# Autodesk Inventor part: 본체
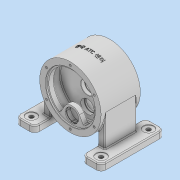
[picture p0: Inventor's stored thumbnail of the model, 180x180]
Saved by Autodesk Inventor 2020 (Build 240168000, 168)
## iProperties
Created: 2025-12
Part Number: 본체
Material: 일반
Document SubType Name: Modeling
Designer: PC2-06
Density: 1 g/cm^3
Appearance: 기본값
Mass: 2121.14 g
Surface Area: 3029.78 cm^2
Volume: 2121.14 cm^3
Author: PC2-06
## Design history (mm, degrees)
sketch "스케치1"
  geometry: L1 (0, 62)-(0, -62); L2 (0, 62)-(78, 62); L3 (78, 62)-(78, 57); L4 (78, 57)-(73, 57); L5 (73, 57)-(73, 43); L6 (76, 40)-(84, 40); L7 (87, 37)-(87, 11); L8 (84, 8)-(21, 8); L9 (21, 8)-(21, -3.4); L10 (20.4, -4)-(19, -4); L11 (19, -4)-(19, -8); L12 (19, -8)-(84, -8); L13 (87, -11)-(87, -37); L14 (84, -40)-(73, -40); L15 (73, -40)-(73, -57); L16 (73, -57)-(78, -57); L17 (78, -57)-(78, -62); L18 (78, -62)-(0, -62); L19 (78, 62)-(97, 62); L20 (97, 62)-(97, -62); L21 (97, -62)-(78, -62); L22 (76, 40)-(73, 40); L23 (73, 40)-(73, 43); A1 r 0.6 centre (20.4, -3.4) between (20.4, -4) and (21, -3.4); A2 r 3 centre (84, 37) between (87, 37) and (84, 40); A3 r 3 centre (84, 11) between (84, 8) and (87, 11); A4 r 3 centre (84, -11) between (87, -11) and (84, -8); A5 r 3 centre (84, -37) between (84, -40) and (87, -37); 7 further points
  constraints: 47 end point, 16 perpendicular, 14 point on line, 10 point on circle, 10 tangent, 5 centre point, 3 horizontal, 1 coincident, 1 collinear, 1 midpoint, 1 vertical
  dimensions: "d0" = 156 diameter of L3 L1; "d1" = 146 diameter of L5 L1; "d2" = 174 diameter of L7 L1; "d3" = 42 diameter of L9 L1; "d4" = 38 diameter of L11 L1; "d5" = 174 diameter of L13 L1; "d6" = 5 distance between parallel lines of L4 L2; "d7" = 22 distance between parallel lines of L2 L6; "d8" = 32 distance between parallel lines of L8 L6; "d9" = 32 distance between parallel lines of L14 L12; "d10" = 22 distance between parallel lines of L18 L14; "d11" = 5 distance between parallel lines of L18 L16; "d12" = 124 distance between parallel lines of L18 L2; "d13" = 12 distance between parallel lines of L10 L8; "d14" = 194 diameter of L20 L1; "d16" = 0.6 radius of A1 (derived)
revolve "회전1" sketch "스케치1" stored, may be unused: angle "d15" = 90 deg
sketch "스케치2"
  geometry: L1 (-21, -3.4)-(21, -3.4) reference; L2 (-21, 8)-(21, 8) reference; L3 (-19, -8)-(19, -8) reference; L4 (-19, -4)-(19, -4) reference; L5 (-84, 8)-(84, 8) reference; L6 (-31.5, 8)-(-31.5, -2.768); L7 (-32.1, -3.368)-(-33.5, -3.368); L8 (-33.5, -3.368)-(-33.5, -8); L9 (-52.5, 8)-(-52.5, -8); L10 (-84, -8)-(84, -8) reference; A1 r 0.6 centre (-32.1, -2.768) between (-32.1, -3.368) and (-31.5, -2.768); 1 further point
  constraints: 8 end point, 3 perpendicular, 3 point on line, 2 point on circle, 2 tangent, 1 centre point, 1 vertical
  dimensions: "d18" = 42 diameter of L6 L9; "d19" = 38 diameter of L8 L9; "d20" = 52.5 horizontal distance of L9.end point (0, 0); "d21" = 0.6 radius of A1
revolve "회전2" sketch "스케치2" stored, may be unused: angle "d22" = 90 deg
sketch "스케치3"
  geometry: L1 (23.383, -39)-(39.648, -67.172); L2 (-23.383, -39)-(-39.648, -67.172); C1 r 21 at (0, -52.5) reference; C2 r 21 at (0, -52.5); A1 r 27 centre (0, -52.5) between (23.383, -39) and (-23.383, -39); A2 r 78 centre (0, 0) between (39.648, -67.172) and (-39.648, -67.172) reference; 1 further point
  constraints: 4 end point, 4 point on circle, 2 centre point, 2 coincident, 2 tangent, 1 horizontal alignment
  dimensions: "d23" = 54 diameter of A1; "d24" = 42 diameter of C2; "d25" = 60 deg angle of L1 L2
extrude "돌출1" join sketch "스케치3" distance "d26" = 17; taper "d27" = 0 deg
fillet "모깎기1" dims "d30" = 3
node "작업 평면1"
sketch "스케치4"
  geometry: L1 (120, -100)-(90, -100); L2 (75, -85)-(75, 85); L3 (90, 100)-(120, 100); L4 (135, 85)-(135, -85); L5 (-90, -100)-(-120, -100); L6 (-135, -85)-(-135, 85); L7 (-120, 100)-(-90, 100); L8 (-75, 85)-(-75, -85); A1 r 15 centre (120, -85) between (120, -100) and (135, -85); A2 r 15 centre (120, 85) between (135, 85) and (120, 100); A3 r 15 centre (90, 85) between (90, 100) and (75, 85); A4 r 15 centre (90, -85) between (75, -85) and (90, -100); A5 r 15 centre (-90, -85) between (-90, -100) and (-75, -85); A6 r 15 centre (-120, -85) between (-135, -85) and (-120, -100); A7 r 15 centre (-120, 85) between (-120, 100) and (-135, 85); A8 r 15 centre (-90, 85) between (-75, 85) and (-90, 100); 3 further points
  constraints: 16 end point, 16 point on circle, 16 tangent, 8 centre point, 7 equal radius, 4 parallel, 2 horizontal, 2 horizontal alignment, 2 midpoint, 2 perpendicular
  dimensions: "d32" = 200 distance between parallel lines of L3 L1; "d33" = 60 distance between parallel lines of L2 L4; "d34" = 60 distance between parallel lines of L6 L8; "d35" = 15 radius of A1; "d36" = 200 distance between parallel lines of L7 L5; "d37" = 150 distance between parallel lines of L8 L2; "d38" = 75 distance from line of L2 point (0, 0)
extrude "돌출3" join sketch "스케치4" distance "d39" = 20; taper "d40" = 0 deg
sketch "스케치5"
  geometry: L1 (-75, -85)-(-75, 85) reference; L2 (-75, 50)-(-97, 50); L3 (-97, 50)-(-97, -50); L4 (-97, -50)-(-75, -50); L5 (-75, -50)-(-75, 50); L6 (75, 85)-(75, -85) reference; L7 (75, 50)-(97, 50); L8 (97, 50)-(97, -50); L9 (97, -50)-(75, -50); L10 (75, -50)-(75, 50); 5 further points
  constraints: 16 end point, 4 parallel, 2 horizontal, 2 horizontal alignment, 2 midpoint, 2 perpendicular, 2 point on line
  dimensions: "d41" = 22 distance of L4.end L3.end; "d42" = 100 distance of L3.end L2.end; "d43" = 22 distance between parallel lines of L8 L6; "d44" = 100 distance between parallel lines of L9 L7
extrude "돌출4" join sketch "스케치5" stored distance "d45" = 20; taper "d46" = 0 deg
sketch "스케치6"
  geometry: 5 further points
  constraints: 2 vertical alignment, 1 horizontal alignment
  dimensions: "d47" = 150 distance of point (-110, -75) point (-110, 75); "d48" = 150 distance of point (110, -75) point (110, 75); "d49" = 220 distance of point (110, -75) point (-110, -75); "d50" = 110 horizontal distance of point (110, -75) point (0, 0); "d51" = 75 vertical distance of point (0, 0) point (-110, 75)
hole "구멍1" sketch "스케치6" at (-110, 75), (-110, -75), (110, -75), (110, 75) diameter "d52" = 13.5; stored, may be unused: countersink angle "d56" = 82 deg, drill point angle "d58" = 118 deg; dims "d53" = 6, "d54" = 33, "d55" = 2, "d57" = 8
sketch "스케치7"
  geometry: L1 (-75, -120)-(-75, -100) reference; L2 (-75, -112)-(-36.6, -89.83); L3 (-135.8, -120)-(135.8, -120) reference; L4 (-75, -100)-(-75, -61.514) reference; A1 r 97 centre (0, 0) between (-36.6, -89.83) and (-75, -61.514) reference; 1 further point
  constraints: 2 end point, 1 point on circle, 1 point on line
  dimensions: "d59" = 8 distance from line of L3 L2.start; "d60" = 60 deg angle of L2 L4
sketch "스케치8"
  geometry: L1 (-31.5, 40)-(-72.802, 40) reference; L2 (-72.802, 57)-(-31.5, 57) reference; L3 (-40.5, 40)-(-66.914, 40) reference; L4 (-52.151, 57)-(-52.151, 40); L5 (-31.151, 57)-(-31.151, 53.95); L6 (-31.151, 53.95)-(-29.901, 53.95); L7 (-29.901, 53.95)-(-29.901, 52); L8 (-29.901, 52)-(-31.151, 52); L9 (-31.151, 52)-(-31.151, 40); L10 (-31.151, 57)-(-52.151, 57); L11 (-31.151, 40)-(-52.151, 40); 5 further points
  constraints: 16 end point, 5 point on line, 4 perpendicular, 3 midpoint, 1 collinear, 1 horizontal, 1 vertical, 1 vertical alignment
  dimensions: "d61" = 44.5 diameter of L7 L4; "d62" = 42 diameter of L5 L4; "d63" = 1.95 distance between parallel lines of L8 L6; "d64" = 12 distance between parallel lines of L1 L8
revolve "회전3" sketch "스케치8" stored, may be unused: angle "d65" = 90 deg
feature "리브1" dims "d66" = 1, "d67" = 12, "d68" = 0, "d69" = 0, "d70" = 1, "d71" = 1
sketch "스케치9"
  geometry: C1 r 85 at (0, 0); 3 further points
  constraints: 2 vertical alignment, 1 centre point, 1 coincident, 1 other
  dimensions: "d72" = 170 diameter of C1
hole "구멍2" sketch "스케치9" at (0, 87) diameter "d73" = 6.647; stored, may be unused: countersink angle "d77" = 82 deg, drill point angle "d79" = 118 deg; dims "d74" = 16, "d75" = 19.05, "d76" = 4.775, "d78" = 18
sketch "스케치10"
  geometry: C1 r 85 at (0, 0); 1 further point
  constraints: 1 centre point, 1 coincident
  dimensions: "d80" = 170 diameter of C1
chamfer "모따기1" distance "d84" = 1; stored, may be unused: second distance "d85" = 2, angle "d86" = 45 deg
fillet "모깎기2" dims "d87" = 3
sketch "스케치11"
  geometry: C1 r 6.75 at (-110, 75) reference; 2 further points
  constraints: 1 coincident, 1 other
fillet "모깎기3" dims "d88" = 3
feature "엠보싱1" dims "d0" = 156, "d1" = 146, "d2" = 174, "d3" = 42, "d4" = 38, "d5" = 174, "d6" = 5, "d7" = 22, "d8" = 32, "d9" = 32, "d10" = 22, "d11" = 5, "d12" = 124, "d13" = 12, "d14" = 194, "d16" = 0.6 (derived), "d89" = 0.5, "d90" = 0
node "솔리드1"
mirror "미러1"
pattern_circular "원형 패턴1" dims angle "d82" = 360 deg
mirror "미러2"
node "투영된 루프1"
node "투영된 루프2"
feature "A9D066F2-1C7D-4E18-AEED-F7BC21143FA4" dims "d52" = 13.5, "d53" = 6, "d54" = 33, "d55" = 2, "d56" = 82 deg, "d57" = 8, "d58" = 118 deg
